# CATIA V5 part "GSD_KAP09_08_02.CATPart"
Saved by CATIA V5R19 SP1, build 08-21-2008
Part number: GSD_REPETITION_07
Description: Beispielmodell. PowerCopy erzeugen  Maik Hertha IT Consultants
Bounding box of the stored display mesh (mm): x -29.841 to 13.746, y -10 to 40, z 36.232 to 53.986
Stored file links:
  \GSD_BUCH_UEBUNG\GSD_KAP09_08_02.CATPart
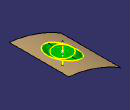
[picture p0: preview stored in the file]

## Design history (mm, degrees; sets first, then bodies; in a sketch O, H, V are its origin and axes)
AxisSystem1 "Absolute Axis System": origin (0, 0, 0), X (1, 0, 0), Y (0, 1, 0), Z (0, 0, 1)
Set1 "Referenz_PC"
  Line1 "Ausrichtung": stored without definition
  DatumSurface1 "Referenzflaeche"
  Intersect1 "Referenzpunkt": ToIntersect1 DatumSurface1, ToIntersect2 Line1
  Set2 "Template"
    Plane1: type Normal, Curve Line1, RefPoint Intersect1
    Sketch1 on Plane1, origin (-6.428, 14.4636, 46.9865), H (0, -1, 0), V (1, 0, 0)
      circle A1 centre (0, 0) radius 7.5
      radius A1 = 7.5
    Split1: ToCut Plane1, Intersections {intersect ToIntersect1 Plane1, ToIntersect2 Sketch1}, Cutting Sketch1
    Extrude1: Lim1 13, Lim2 13, Element1 Sketch1, Direction Plane1
    Offset1: Length 5, Offset Extrude1
    Split2: ToCut DatumSurface1, Intersections {intersect ToIntersect1 DatumSurface1, ToIntersect2 Offset1}, Cutting Offset1
    Blend1: StartLimit {blendlimit Support Split1, Curve {intersect ToIntersect1 Plane1, ToIntersect2 Sketch1}, Point {extremum Reference {intersect ToIntersect1 Plane1, ToIntersect2 Sketch1}, Direction2 (0, 0, 1), Direction3 (0, 0, 1), Direction (0, 1, 0)}}, EndLimit {blendlimit Support Split2, Curve {intersect ToIntersect1 DatumSurface1, ToIntersect2 Offset1}, Point {extremum Reference {intersect ToIntersect1 DatumSurface1, ToIntersect2 Offset1}, Direction2 (0, 0, 1), Direction3 (0, 0, 1), Direction (0, 1, 0)}}
Body1 (main body)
